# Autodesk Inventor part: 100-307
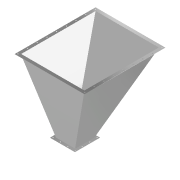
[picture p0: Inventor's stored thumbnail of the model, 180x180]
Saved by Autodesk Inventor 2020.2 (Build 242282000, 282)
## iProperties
Created: 2011-01
Part Number: 100-307
Document SubType Name: Modeling
Designer: F.Stasiak
Density: 1 g/cm^3
Material: Ogólny
Appearance: Chrom — polerowany
Company: Fabian Stasiak CAD Consulting
Manager: www.cadconsulting.pl
Author: F.Stasiak
Subject: Zbiór ćwiczeń. Autodesk Inventor 2020. Kurs podstawowy
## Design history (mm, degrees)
node "Płaszczyzna konstrukcyjna1"
sketch "Szkic3"
  geometry: L1 (425, 700)-(-425, 700); L2 (-425, 700)-(-425, -300); L3 (-425, -300)-(425, -300); L4 (425, -300)-(425, 700); 2 further points
  constraints: 8 end point, 2 parallel, 1 horizontal, 1 midpoint, 1 perpendicular, 1 vertical alignment
  dimensions: "d3" = 850 distance of L3.end L2.end; "d4" = 1000 distance of L2.end L1.end; "d5" = 300 distance from line of L3 point (0, 0)
sketch "Szkic4"
  geometry: L1 (125, 125)-(125, -125) reference; L2 (-125, 125)-(125, 125) reference; L3 (-125, -125)-(-125, 125) reference; L4 (125, -125)-(-125, -125) reference; 1 further point
feature "Wyciągnięcie złożone2" sketch "Szkic3", "Szkic4" dims "d10" = 0, "d11" = 90 deg, "d12" = 0, "d13" = 90 deg
feature "Skorupa1" dims "d14" = 3
sketch "Szkic5"
  geometry: L1 (-168, 168)-(-168, -168) reference; L2 (-168, -168)-(168, -168) reference; L3 (168, -168)-(168, 168) reference; L4 (168, 168)-(-168, 168) reference; L5 (-125, -125)-(-125, 125) reference; L6 (-125, 125)-(125, 125) reference; L7 (125, 125)-(125, -125) reference; L8 (125, -125)-(-125, -125) reference; C1 r 6.5 at (148, 49.333) reference; C2 r 6.5 at (148, -49.333) reference; C3 r 6.5 at (148, -148) reference; C4 r 6.5 at (49.333, -148) reference; C5 r 6.5 at (-49.333, -148) reference; C6 r 6.5 at (-148, -148) reference; C7 r 6.5 at (-148, -49.333) reference; C8 r 6.5 at (-148, 49.333) reference; C9 r 6.5 at (-148, 148) reference; C10 r 6.5 at (-49.333, 148) reference; C11 r 6.5 at (49.333, 148) reference; C12 r 6.5 at (148, 148) reference; 1 further point
extrude "Wyciągnięcie proste2" join sketch "Szkic5" distance "d15" = 3; taper "d16" = 0 deg
sketch "Szkic6"
  geometry: L1 (0, -1006.599)-(0, 0) reference; L2 (0, 0)-(856.315, 0) reference; L3 (856.315, 0)-(856.315, -1006.599) reference; L4 (856.315, -1006.599)-(0, -1006.599) reference; L5 (896.315, -1046.599)-(896.315, 40); L6 (896.315, 40)-(-40, 40); L7 (-40, 40)-(-40, -1046.599); L8 (-40, -1046.599)-(896.315, -1046.599); 1 further point
  constraints: 8 end point, 3 other
  dimensions: "d17" = 40 distance between parallel lines of L5 L3
extrude "Wyciągnięcie proste3" join sketch "Szkic6" distance "d18" = 3; taper "d19" = 0 deg
sketch "Szkic7"
  geometry: L1 (856.315, -1006.599)-(0, -1006.599) reference; L2 (0, -1006.599)-(0, 0) reference; L3 (0, 0)-(856.315, 0) reference; L4 (856.315, 0)-(856.315, -1006.599) reference; L5 (896.315, -1046.599)-(896.315, 40) reference; L6 (896.315, 40)-(-40, 40) reference; L7 (-40, 40)-(-40, -1046.599) reference; L8 (-40, -1046.599)-(896.315, -1046.599) reference; L9 (-20, 40)-(-20, -1046.599); 2 further points
  constraints: 2 end point, 2 point on line, 1 midpoint, 1 perpendicular
  dimensions: "d20" = 20 distance between parallel lines of L9 L7
hole "Hole1" sketch "Szkic7" at (-20, -503.299) diameter "d21" = 13; stored, may be unused: countersink angle "d25" = 90 deg, drill point angle "d27" = 118 deg; dims "d22" = 6, "d23" = 4, "d24" = 2, "d26" = 8
mirror "Odbicie lustrzane1"
node "Bryła2"
pattern_linear "Szyk prostokątny1" dims "d30" = 130, "d33" = 130
node "Odniesienie6"
node "Odniesienie7"
node "Odniesienie8"
node "Odniesienie9"
node "Odniesienie10"
node "Pętla rzutowana1"
other parameters: "d2" = 914
